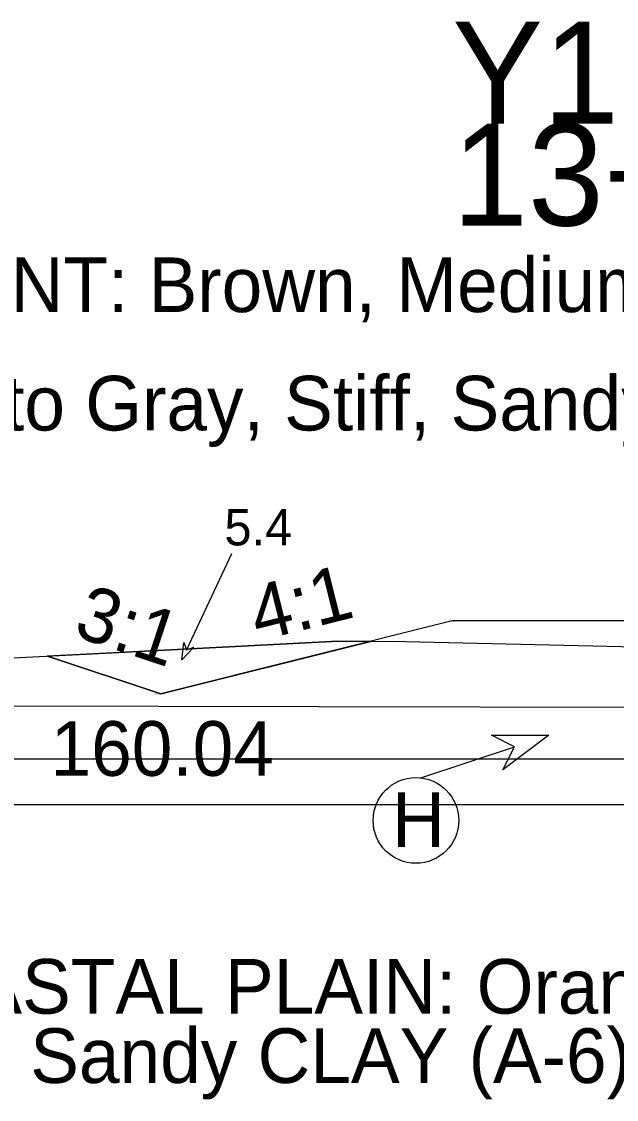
# Model space of a CAD drawing. Extents: x -516 to 303, y -10 to 5017.
# Drawn here: x 128.17 to 144.51, y 3491.91 to 3521.49 of the extents above; entities that cross this region are included whole.
import ezdxf

# ---------------------------------------------------------------- set-up
doc = ezdxf.new("R2010")
doc.units = 0
for name, color, linetype in [('Exist Cross Section Cell', 7, 'Continuous'), ('Exist XS Ground Line', 7, 'Continuous'), ('Misc Plan Tools Cell', 7, 'Continuous'), ('Prop CMT Slope Grass', 7, 'Continuous'), ('Prop Road Sect_ Material - Bubble + Leader + Bubble Tx', 7, 'Continuous'), ('Prop Road Sect_ Material - Contact (General - Major)', 7, 'Continuous'), ('Prop Road Sect_ Material - Contact (General - Minor)', 7, 'Continuous'), ('Prop Road Sect_ Material - Tx (Composite Desc)', 7, 'Continuous'), ('Prop Road Sect_ Misc - Drafting Aid (Tx - small)', 7, 'Continuous'), ('Prop Road Sect_ Recs - UUC (Outline)', 7, 'Continuous'), ('Prop Road Sect_ Recs - UUC (pattern)', 7, 'Continuous'), ('Prop XS Ditch Standard Text', 7, 'Continuous'), ('Prop XS Side Slope Text', 7, 'Continuous'), ('Scratch_Level_0', 7, 'Continuous')]:
    doc.layers.add(name, color=color, linetype=linetype)

msp = doc.modelspace()

# ---------------------------------------------------------------- linework, layer by layer
at = {"layer": 'Exist Cross Section Cell'}
msp.add_line((0, 3500), (150, 3500), dxfattribs=at)
at = {"layer": 'Exist XS Ground Line'}
msp.add_lwpolyline([(125.205, 3503.894), (131.752, 3504.218), (136.683, 3504.474), (138.318, 3504.484), (148.612, 3504.249), (149.068, 3504.229), (150, 3504.197), (151.323, 3504.152), (153.226, 3504.101), (154.223, 3504.074), (155.681, 3504.024), (157.11, 3503.973), (158.112, 3503.939), (159.309, 3503.9), (160.012, 3503.878), (163.151, 3503.785), (163.586, 3503.765), (164.534, 3503.718), (165.952, 3503.61), (166.307, 3503.585)], dxfattribs=at)
at = {"layer": 'Misc Plan Tools Cell'}
msp.add_lwpolyline([(141.077, 3501.906), (142.659, 3501.905), (141.393, 3500.957), (141.71, 3501.59)], close=True, dxfattribs=at)
at = {"layer": 'Prop CMT Slope Grass'}
for p, q in [((140, 3505.04), (132, 3503.04)), ((146, 3505.04), (140, 3505.04)), ((132, 3503.04), (128.891, 3504.076))]:
    msp.add_line(p, q, dxfattribs=at)
at = {"layer": 'Prop Road Sect_ Material - Bubble + Leader + Bubble Tx'}
msp.add_line((139.143, 3500.736), (141.71, 3501.59), dxfattribs=at)
msp.add_circle((139.006, 3499.565), 1.176, dxfattribs=at)
at = {"layer": 'Prop Road Sect_ Material - Contact (General - Major)'}
msp.add_line((176.847, 3502.602), (116.479, 3502.719), dxfattribs=at)
at = {"layer": 'Prop Road Sect_ Material - Contact (General - Minor)'}
msp.add_line((112.368, 3501.254), (189.704, 3501.254), dxfattribs=at)
at = {"layer": 'Prop Road Sect_ Misc - Drafting Aid (Tx - small)'}
msp.add_line((133.939, 3506.887), (132.709, 3504.249), dxfattribs=at)
msp.add_lwpolyline([(132.909, 3504.322), (132.581, 3503.976), (132.636, 3504.45), (132.709, 3504.249)], close=True, dxfattribs=at)
at = {"layer": 'Prop Road Sect_ Recs - UUC (Outline)'}
msp.add_lwpolyline([(132, 3503.04), (137.762, 3504.48), (136.683, 3504.474), (131.752, 3504.218), (128.891, 3504.076)], close=True, dxfattribs=at)
at = {"layer": 'Prop Road Sect_ Recs - UUC (pattern)'}
msp.add_lwpolyline([(132, 3503.04), (137.762, 3504.48), (136.683, 3504.474), (131.752, 3504.218), (128.891, 3504.076), (132, 3503.04)], dxfattribs=at)

# ---------------------------------------------------------------- texts
at = {"layer": 'Exist Cross Section Cell'}
for s, p in [('Y1', (140, 3518.692)), ('13+50.00 / 1', (140, 3515.892))]:
    msp.add_text(s, height=2.8, dxfattribs=at).set_placement(p)
at = {"layer": 'Prop Road Sect_ Material - Tx (Composite Desc)'}
for s, p in [('ROADWAY EMBANKMENT: Brown, Medium Stiff to Stiff, Silty CLAY (A-7-6), Highly Plastic, Moist', (105.475, 3513.518)), ('COASTAL PLAIN: Black to Gray, Stiff, Sandy SILT (A-4), Moist (Black Creek Formation)', (105.4, 3510.268)), ('H', (138.353, 3498.833)), ('COASTAL PLAIN: Orange-Brown and Gray, Soft to Medium ', (123.842, 3494.262)), ('Stiff, Sandy CLAY (A-6), Moist to Wet (Black Creek Formation)', (123.842, 3492.36))]:
    msp.add_text(s, height=1.5, dxfattribs=at).set_placement(p)
at = {"layer": 'Prop Road Sect_ Misc - Drafting Aid (Tx - small)'}
msp.add_text('5.4', height=1, dxfattribs=at).set_placement((133.747, 3507.114))
at = {"layer": 'Prop XS Ditch Standard Text'}
msp.add_text('160.04', height=1.5, dxfattribs=at).set_placement((128.971, 3500.79))
at = {"layer": 'Prop XS Side Slope Text'}
for s, rotation, p in [('4:1', 14.0362, (134.665, 3504.479)), ('3:1', 341.5668, (129.555, 3504.646))]:
    msp.add_text(s, height=1.5, rotation=rotation, dxfattribs=at).set_placement(p)
at = {"layer": 'Scratch_Level_0'}
for s, p in [('LT_GS_OS_CTL', (139.894, 3505.03)), ('LT_Slope_Cut', (128.787, 3504.066)), ('LT_SS_Ditch_Base_Out', (131.821, 3503.03))]:
    msp.add_text(s, height=0.02, dxfattribs=at).set_placement(p)

doc.saveas('drawing.dxf')
